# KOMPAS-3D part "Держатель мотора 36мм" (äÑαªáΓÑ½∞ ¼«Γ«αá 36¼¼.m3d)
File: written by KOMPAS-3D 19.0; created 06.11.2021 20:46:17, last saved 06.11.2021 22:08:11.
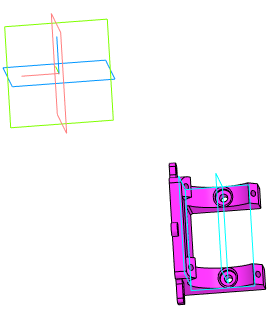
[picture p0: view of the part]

Document properties: Полное имя файла: D:\3D_print\3D проекты Компас 3D\Редуктор (Снова)\Держатель мотора 36мм.m3d

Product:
- Part/product: Держатель мотора 36мм
    Материал: АБС 0603Т ТУ 2214-019-002 03521-96 (density 0 kg/m3)

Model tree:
1. Эскиз:1  (with: Элемент выдавливания:1, Элемент выдавливания:10, Элемент выдавливания:13)  (labels: Reductor\Korpus(2); Держатель мотора 36мм)
2. Нормальная плоскость:1  (with: Элемент выдавливания:1)  (labels: Motor_D36x50; Держатель мотора 36мм; Reductor\Korpus(2))
3. Смещенная плоскость:1
     Расстояние = 18.1
4. Элемент выдавливания:3
     Расстояние 1 = 3
5. Эскиз:2  (with: Элемент выдавливания:1, Элемент выдавливания:3)  (labels: Motor_D36x50; Держатель мотора 36мм)
6. Элемент выдавливания:5  (with: Элемент выдавливания:1)  (labels: Motor_D36x50; Держатель мотора 36мм)
     Расстояние 1 = -50
7. Эскиз:3  (with: Элемент выдавливания:5)
8. Элемент выдавливания:6
     Расстояние 2 = 46.112
9. Эскиз:4  (with: Элемент выдавливания:5, Элемент выдавливания:3)
10. Элемент выдавливания:11
     Расстояние 2 = 40.012
11. Скругление:1  (with: Элемент выдавливания:11)
     Радиус = 2
12. Эскиз:5  (with: Элемент выдавливания:3, Элемент выдавливания:5, Элемент выдавливания:6)
13. Элемент выдавливания:12
     Расстояние 2 = 51.4307
14. Эскиз:6  (with: Элемент выдавливания:5)
15. Элемент выдавливания:13
     Расстояние 2 = 15
16. Касательная плоскость:1  (with: Элемент выдавливания:5, Элемент выдавливания:1)  (labels: Reductor\Korpus(2); Держатель мотора 36мм)
     Угол = 90
17. Эскиз:7  (with: Элемент выдавливания:12)
18. Элемент выдавливания:14
     Расстояние 1 = 40.6307; Расстояние 2 = 3
19. Скругление:2  (with: Элемент выдавливания:14)
     Радиус = 1
20. Скругление:3  (with: Элемент выдавливания:6)
     Радиус = 1
21. Элемент выдавливания:15  (with: Элемент выдавливания:3, Элемент выдавливания:5)
     Расстояние 2 = 0.888016
22. Элемент выдавливания:16  (with: Элемент выдавливания:3, Элемент выдавливания:5)
     Расстояние 2 = 0.888016
23. Скругление:5  (with: Элемент выдавливания:5)  (labels: АБС 0603Т ТУ 2214-019-002 03521-96)
     Радиус = 3

Referenced files in D:\3D_print\3D проекты Компас 3D\Редуктор (Снова)\: Намоточный станок (Projects 6).a3d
